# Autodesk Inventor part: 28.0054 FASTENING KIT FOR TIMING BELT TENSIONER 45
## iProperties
Created: 2007-06
Part Number: 28.0054 FASTENING KIT FOR TIMING BELT TENSIONER 45
Document SubType Name: Modeling
Designer: Andy Moles
Material: Aluminum-6061
Mass: 121.643 g
Surface Area: 114.236 cm^2
Volume: 44.8868 cm^3
Density: 2.71 g/cm^3
Author: Andy Moles
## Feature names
1. Extrusion1
2. Hole1
